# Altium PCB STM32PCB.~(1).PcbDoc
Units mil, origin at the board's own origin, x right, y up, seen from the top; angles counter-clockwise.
Board outline 2110.03 x 910.03 mil, 2 copper layers (Top Layer, Bottom Layer), stack 65.792 mil thick; 30 components, 49 nets, 163 pads, 181 vias.
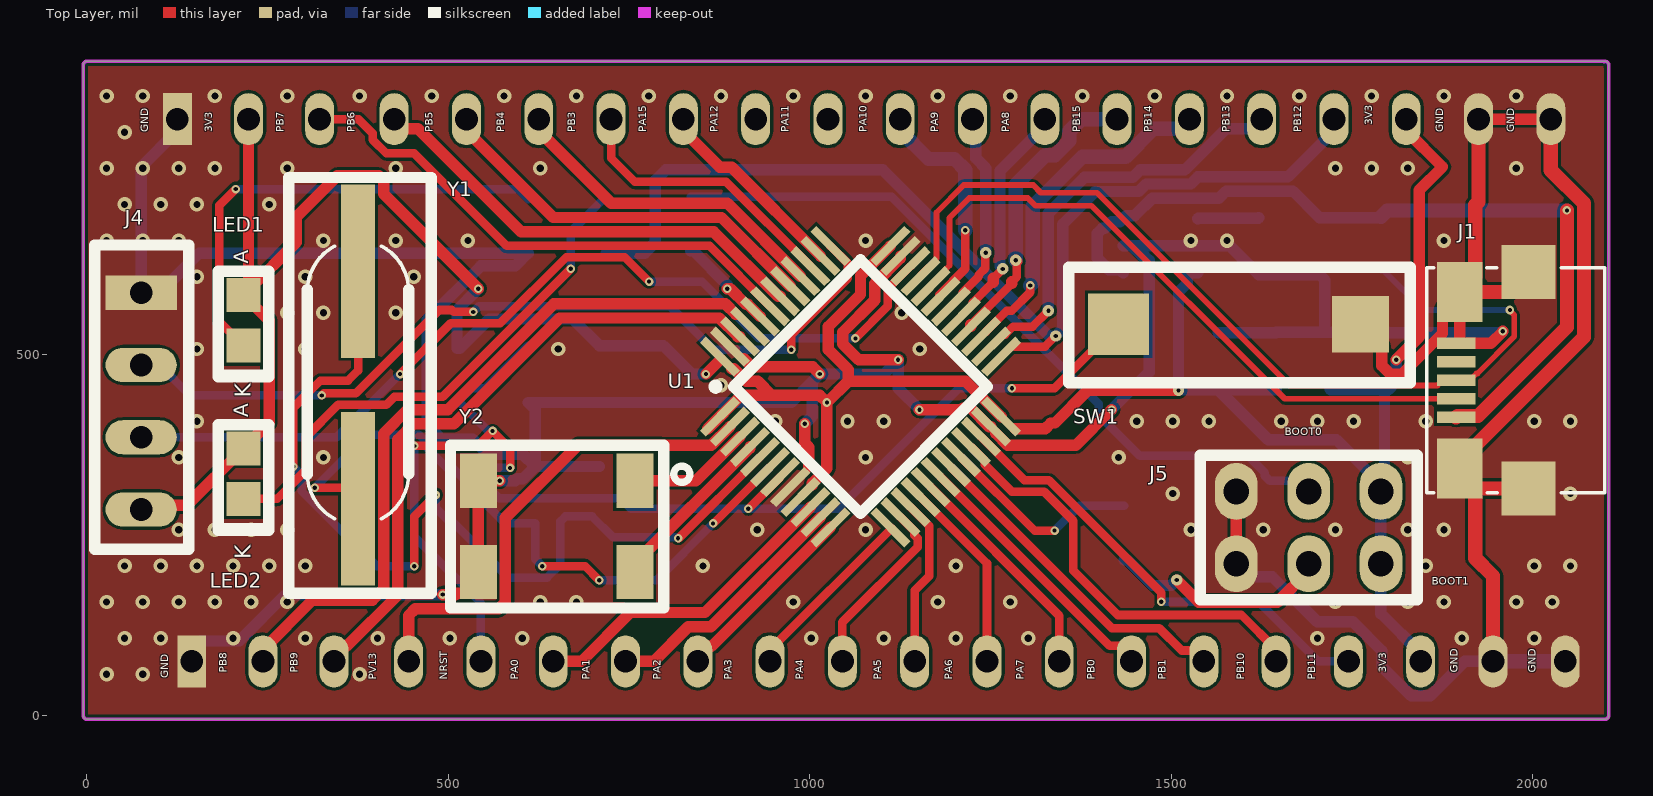
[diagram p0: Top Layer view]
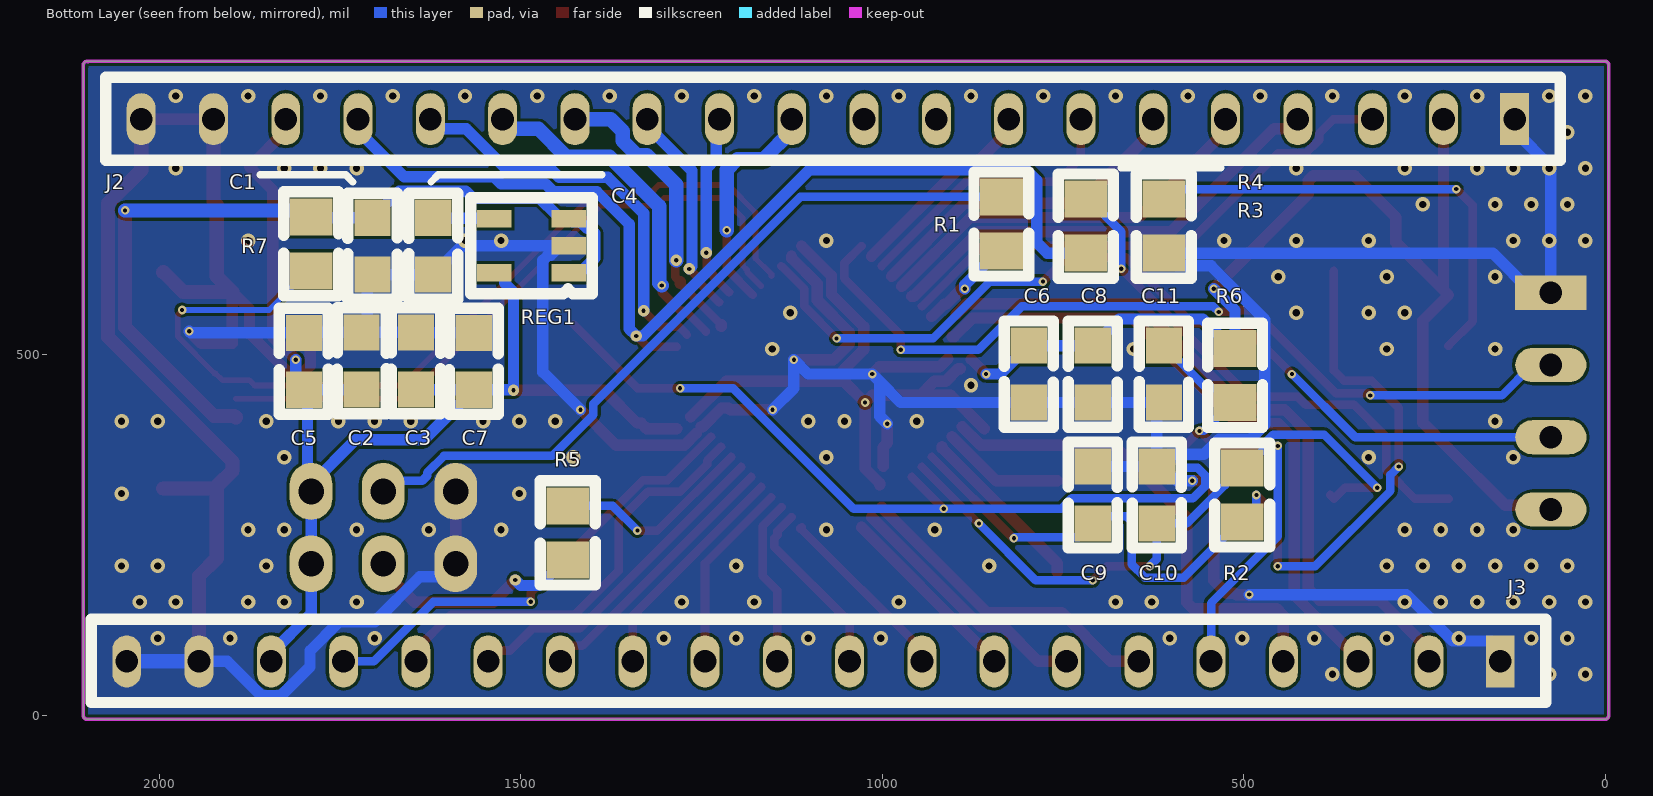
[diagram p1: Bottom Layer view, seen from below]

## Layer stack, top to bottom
Top Solder: solder mask 0.4, Solder Resist, Dk 3.5
Top Layer: signal copper 1.4
Dielectric 1: dielectric 62.9921, FR-4, Dk 4.8
Bottom Layer: signal copper 1.4
Bottom Solder: solder mask 0.4, Solder Resist, Dk 3.5

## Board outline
-5.02,0 -5.02,900 cw(c0,900) 0,905.01 2097.07,905.01 2098.54,904.8 cw(c2100,900) 2105.01,900 2105.01,0 cw(c2100,0) 2100,-5.02 2.14,-5.02 1.07,-4.9 cw(c0,0)

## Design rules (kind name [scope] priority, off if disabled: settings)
Clearance [All] p1: gap=3.94 ignorepadtopadclearanceinfootprint=TRUE
DiffPairsRouting DiffPair_90DiffPairsRouting [InDifferentialPairClass('diff_90')] p1: maxlimit=10 minlimit=10 mostfreqgap=10 toplayer_minwidth=8 toplayer_maxwidth=8 toplayer_prefwidth=8 bottomlayer_minwidth=8 bottomlayer_maxwidth=8 bottomlayer_prefwidth=8 maxuncoupledlength=500
DiffPairsRouting [All] p2: maxlimit=10 minlimit=10 mostfreqgap=10 toplayer_minwidth=15 toplayer_maxwidth=15 toplayer_prefwidth=15 bottomlayer_minwidth=15 bottomlayer_maxwidth=15 bottomlayer_prefwidth=15 maxuncoupledlength=500
MatchedLengths DiffPair_90MatchedLengths [InDifferentialPairClass('diff_90')] p1: tolerance=1000 checknetsindiffpair=FALSE checkdiffpairvsdiffpair=TRUE checkxsignals=TRUE checkothers=TRUE
PolygonConnect [All] p1: connectstyle=Direct reliefconductorwidth=10 reliefentries=4 polygonreliefangle="90 Angle" airgapwidth=10
RoutingVias [All] p1: holewidth=8 width=15 viastyle="Through Hole" minholewidth=5 minwidth=10 maxholewidth=10 maxwidth=20
SolderMaskExpansion [All] p1: expansion=4 istentingtop=FALSE
Width [All] p1: maxlimit=39.37 minlimit=11.81 preferedwidth=19.68
29 further rules are at their usual default settings.

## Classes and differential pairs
differential pair class diff_90: D
component class Controller_Page: C5 C6 C7 C8 C9 C10 C11 J5 LED1 LED2 R1 R2 R3 R4 R5 R6 SW1 U1 Y1 Y2
component class Connector_Page: C1 C2 C3 C4 J1 J2 J3 R7 REG1
differential pair D: +D_P -D_N

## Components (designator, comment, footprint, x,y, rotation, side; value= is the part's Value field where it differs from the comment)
C1 "0.1uF" CAP_0805 1705,649.37 r90 bottom
C2 "0.1uF" CAP_0805 1720,490.63 r270 bottom
C3 "1uF" CAP_0805 1645,490.63 r270 bottom
C4 "22pF" CAP_0805 1620.87,649.37 r90 bottom
C5 "0.1uF" CAP_0805 1800,490 r270 bottom
C6 "0.1uF" CAP_0805 797.24,472.44 r90 bottom
C7 "0.1uF" CAP_0805 1565,490 r270 bottom
C8 "0.1uF" CAP_0805 708.66,472.44 r90 bottom
C9 "22pF" CAP_0805 708.66,305.12 r270 bottom
C10 "22pF" CAP_0805 620.08,305.12 r270 bottom
C11 "0.1uF" CAP_0805 610.23,472.44 r90 bottom
J1 "MICRO USB2.0" CON_10118192-0001LF_SMD 1944.12,463.8 r90 top
J2 "20X1 Bergstrip" CON20_100_40D72_TH_ST 125,825 r270 bottom locked
J3 "20X1 Bergstrip" CON20_100_40D72_TH_ST 145,75 r270 bottom locked
J4 "4X1 Bergstrip" CON4_100_40D72_TH_ST_MALE 75,585 r0 top
J5 "2X3 Berg Strip" CON6_100_59D78_TH_ST_Duplicate 1790,310 r180 top
LED1 "RED LED" LED_0805 216.53,546.81 r90 top
LED2 "RED LED" LED_0805 216.54,334.65 r90 top
R1 "10K" RES_0805 835,680 r270 bottom
R2 "10Mohm" RES_0805 501.97,305.12 r270 bottom
R3 "1K" RES_0805 610.24,677.17 r270 bottom
R4 "1K" RES_0805 718.51,677.17 r270 bottom
R5 "10K" RES_0805 1435,252.6 r90 bottom
R6 "10K" RES_0805 511.81,470.48 r270 bottom
R7 "10K" RES_0805 1790,652.6 r270 bottom
REG1 "RT9193-33GB" SOT23-5 1485,650 r90 bottom
SW1 "TACT SWITCH" SW_342_SMD 1761.81,541.34 r0 top
U1 "STM32F103C8T6" LQFP-48_19.6_393_58X11_SMD 1070,455 r45 top locked
Y1 "8MHz" XTAL_314_240X47_SMD 375,614.96 r270 top locked
Y2 "32.768KHz" "XTAL_MC-405 32.7680K-G3" 757.87,198.82 r180 top

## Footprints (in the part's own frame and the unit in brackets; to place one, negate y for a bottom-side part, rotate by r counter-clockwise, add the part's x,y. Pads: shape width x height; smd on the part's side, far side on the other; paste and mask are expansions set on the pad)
CAP_0805 [mil] "Ceramic Capacitor"
  rect 50x50 smd mask+3: 1(-39.37,0) 2(39.37,0)
  silkscreen extent -73,-34 73,34, body extent -39,-25 39,25, height 31
CON4_100_40D72_TH_ST_MALE [mm] "Berg Strip"
  rect 2.5x1.2 hole 0.8: 1(0,0)
  oval 2.5x1.2 hole 0.8: 2(0,-2.54) 3(0,-5.08) 4(0,-7.62)
  round 1.016 on Top Overlay: ""(2.311,0.178)
  silkscreen extent -1.63,-9.02 1.68,1.68, body extent -1.14,-8.76 1.4,1.4, height 8.55
CON6_100_59D78_TH_ST_Duplicate [mm] "Berg strip"
  oval 1.5x2 hole 0.9: 1(0,0) 2(0,2.54) 3(2.54,0) 4(2.54,2.54) 5(5.08,0) 6(5.08,2.54)
  silkscreen extent -1.27,-1.27 6.35,3.81, body extent -1.07,-1.27 6.15,3.56, height 8.18
CON20_100_40D72_TH_ST [mil] "Berg strip"
  rect 72x40 hole 31.5: 1(0,0)
  oval 72x40 hole 31.5: 2(0,-98.43) 3(0,-196.85) 4(0,-300) 5(0,-400) 6(0,-500) 7(0,-600) 8(0,-700) 9(0,-800) 10(0,-900) 11(0,-1000) 12(0,-1100) 13(0,-1200) 14(0,-1300) 15(0,-1400) 16(0,-1500) 17(0,-1600) 18(0,-1700) 19(0,-1800) 20(0,-1900)
  round 40 on Bottom Overlay: ""(83,2.57)
  silkscreen extent -58,-1949 57,63, body extent -51,-1949 47,51, height 323
CON_10118192-0001LF_SMD [mm] "USB2.0 MICRO"
  rect 0.4x1.35 smd: 1(-1.3,1.275) 2(-0.65,1.275) 3(0,1.275) 4(0.65,1.275) 5(1.3,1.275)
  rect 2.1x1.6 smd: 6(-3.1,1.15) 7(3.1,1.15)
  rect 1.9x1.9 smd: 8(-3.8,-1.275) 9(3.8,-1.275)
  silkscreen extent -3.95,-3.94 3.95,2.3, body extent -4.04,-3.94 4.04,1.66, height 2.81
LED_0805 [mm] "LED"
  rect 1.2x1.2 smd mask+0.076: A(0.889,0) K(-0.889,0)
  silkscreen extent -1.99,-0.89 1.73,0.89, body extent -1.01,-0.62 1.01,0.63, height 1.1
LQFP-48_19.6_393_58X11_SMD [mm] "48LQFP"
  rect 1.7x0.3 smd mask+0.076: 1(-4.238,2.75) 2(-4.238,2.25) 3(-4.238,1.75) 4(-4.238,1.25) 5(-4.238,0.75) 6(-4.238,0.25) 7(-4.238,-0.25) 8(-4.238,-0.75) 9(-4.238,-1.25) 10(-4.238,-1.75) 11(-4.238,-2.25) 12(-4.238,-2.75) 25(4.238,-2.75) 26(4.238,-2.25) 27(4.238,-1.75) 28(4.238,-1.25) 29(4.238,-0.75) 30(4.238,-0.25) 31(4.238,0.25) 32(4.238,0.75) 33(4.238,1.25) 34(4.238,1.75) 35(4.238,2.25) 36(4.238,2.75)
  rect 0.3x1.7 smd mask+0.076: 13(-2.75,-4.238) 14(-2.25,-4.238) 15(-1.75,-4.238) 16(-1.25,-4.238) 17(-0.75,-4.238) 18(-0.25,-4.238) 19(0.25,-4.238) 20(0.75,-4.238) 21(1.25,-4.238) 22(1.75,-4.238) 23(2.25,-4.238) 24(2.75,-4.238) 37(2.75,4.238) 38(2.25,4.238) 39(1.75,4.238) 40(1.25,4.238) 41(0.75,4.238) 42(0.25,4.238) 43(-0.25,4.238) 44(-0.75,4.238) 45(-1.25,4.238) 46(-1.75,4.238) 47(-2.25,4.238) 48(-2.75,4.238)
  silkscreen extent -3.72,-3.15 3.15,3.72, body extent -4.5,-4.5 4.5,4.5, height 1.7
RES_0805 [mm] "Resister"
  rect 1.3x1.5 smd mask+0.076: 1(0.95,0) 2(-0.95,0)
  silkscreen extent -1.83,-0.97 1.83,0.97, body extent -1,-0.63 1,0.62, height 0.5
SOT23-5 [mm] "CASE: SOT"
  rect 0.62x1.22 smd mask+0.076: 1(-0.953,-1.31) 2(-0.003,-1.31) 3(0.947,-1.31) 4(0.952,1.31) 5(-0.953,1.31)
  silkscreen extent -1.69,-2.14 1.69,2.14, body extent -1.5,-1.5 1.5,1.5, height 1.41
SW_342_SMD [mm] "CASE: SMD"
  rect 2x2 smd: 1(0,0)
  rect 2.15x2.15 smd: 2(-8.5,0)
  silkscreen extent -10.25,-2.06 1.75,2, body extent -7.17,-1.79 -1.17,1.71, height 2.4
XTAL_314_240X47_SMD [mm] "CASE: TH"
  rect 6.096x1.2 smd: 1(0,0) 2(8,0)
  silkscreen extent -3.29,-2.44 11.32,2.57, body extent -2.99,-2.27 10.9,2.41, height 3.05
"XTAL_MC-405 32.7680K-G3" [mm] "Crystal"
  rect 1.3x1.9 smd: 1(0,-3.2) 2(5.5,-3.2) 3(5.5,0) 4(0,0)
  silkscreen extent -1.93,-4.44 6.48,1.27, body extent -1.02,-4.44 6.48,1.27, height 3.6

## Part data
C1 C2 C5 C6 C7 C8 C11: library part CAP_0.1uF-50V-5%-0805, "0.1µF ±5% 50V Ceramic Capacitor X7R 0805 (2012 Metric)", Case/Package="0805 (2012 Metric)", Manufacturer=KEMET, Manufacturing Part Number=C0805C104J5RACTU, Supplier Part Number-1=399-1171-1-ND
C3: library part CAP_1uF-50V-5%-0805, "1µF ±5% 50V Ceramic Capacitor X7R 0805 (2012 Metric)", Case/Package="0805 (2012 Metric)", Manufacturer=Yageo, Manufacturing Part Number=CC0805JKX7R9BB105, Supplier Part Number-1=311-3498-1-ND
C4 C9 C10: library part CAP_22pF-50V-5%-0805, "22pF ±5% 50V Ceramic Capacitor C0G, NP0 0805 (2012 Metric)", Case/Package=0805, Manufacturer=KEMET, Manufacturer Part Number=C0805C220J5GACTU, Supplier Part Number-1=399-1113-1-ND
J1: library part CON-USB_10118192-0002LF-SMD, "USB - micro B USB 2.0 Receptacle Connector 5 Position Surface Mount, Right Angle", Case/Package=SMD, Manufacturer="Amphenol ICC (FCI)", Manufacturing Part Number=10118192-0002LF, Supplier Part Number-1=609-5379-1-ND
J2 J3: library part CON-BS-PLG_20X1-100-TH-ST, "20 pin, 1 row, 2.54mm pitch bergstrip", Case/Package=TH, Manufacturer=NA
J4: library part CON-BS-PLG_4X1-100-TH-ST, "4 pin, 1 row, 2.54mm pitch bergstrip", Case/Package=TH, Manufacturer=NA
J5: library part CON-BS-PLG_2X3-100-TH-ST, "6 pin, 2 row, 2.54mm pitch bergstrip", Case/Package=TH, Manufacturer=NA
LED1 LED2: library part LED-RED_10mA-0805, "Red 621nm LED Indication - Discrete 2V 0805 (2012 Metric)", Case/ Package=0805, Manufacturer="Lite-On Inc.", Manufacturer Part Number=LTST-C170EKT, Supplier Part Number-1=160-1178-1-ND
R1 R5 R6 R7: library part RES_10K-0.125W-1%-0805, "10 kOhms ±1% 0.125W, 1/8W Chip Resistor 0805 (2012 Metric) Moisture Resistant Thick Film", Case/Package=0805, Manufacturer=Yageo, Manufacturing Part Number=RC0805FR-0710KL, Supplier Part Number-1=311-10.0KCRCT-ND
R2: library part RES_10MOHM-0.125W-1%-0805, "10 MOhms ±1% 0.125W, 1/8W Chip Resistor 0805 (2012 Metric) Automotive AEC-Q200, High Voltage Thick Film", Case/Package="0805 (2012 Metric)", Manufacturer="Rohm Semiconductor", Manufacturing Part Number=KTR10EZPF1005, Supplier Part Number-1=RHM10.0MAHCT-ND
R3 R4: library part RES_1K-0.125W-1%-0805, "1 kOhms ±1% 0.125W, 1/8W Chip Resistor 0805 (2012 Metric) Moisture Resistant Thick Film", Case/Package=0805, Manufacturer=垈㎵á, Manufacturer Part Number=RC0805FR-071KL, Supplier Part Number-1=311-1.00KCRCT-ND
REG1: library part REG_3.3V-5.5V-0.3A-SOT-23-5, "Linear Voltage Regulator IC 1 Output 300mA SOT-23-5", Case/ Package=SOT-23-5, Manufacturer="Richtek USA Inc.", Supplier Part Number-1=1028-1014-1-ND
SW1: library part SW_KSR223GLFG-SMD, "Tactile Switch SPST-NO Top Actuated Surface Mount", Case/Package=SMD, Manufacturer=C&K, Manufacturing Part Number=KSR223GLFG, Supplier Part Number-1=401-1704-1-ND
U1: library part "IC-STM32F103C8T6 _1", "ARM® Cortex®-M3 STM32F1 Microcontroller IC 32-Bit 72MHz 64KB (64K x 8) FLASH", Case/Package=48-LQFP, Manufacturer=STMicroelectronics, Supplier Part Number-1=497-6063-ND
Y1: library part XTAL_8MHZ-LFXTAL030234, "Crystals 8MHz 22pF -20C 70C", Case/Package=SMD, Manufacturer="IQD Frequency Products", Manufacturing Part Number=LFXTAL030234Reel, Supplier Part Number-1=449-LFXTAL030234REEL
Y2: library part "XTAL_32.768KHz-MC-405 32.7680K-G3", "Crystals SMD AT XTL MHZ +/-50PPM 12.5 PF 250 T/R", Case/Package=SMD, Manufacturer=Epson, Manufacturing Part Number="MC-405 32.7680K-G3: ROHS", Supplier Part Number-1=732-MC405327680KG3RS

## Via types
v1: diameter 20, hole 10, Top Layer to Bottom Layer, tented both sides, 134 vias
v2: diameter 11.81, hole 5.91, Top Layer to Bottom Layer, 40 vias
v3: diameter 15.75, hole 5.91, Top Layer to Bottom Layer, 7 vias

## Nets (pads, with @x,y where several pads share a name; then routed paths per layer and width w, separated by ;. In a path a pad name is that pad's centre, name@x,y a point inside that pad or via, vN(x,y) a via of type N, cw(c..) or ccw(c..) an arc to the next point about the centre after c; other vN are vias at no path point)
+3V3: C2.2 C3.2 C5.2 C6.2 C7.2 C8.2 J2.2 J2.18 J3.18 J4.4 J5.1 J5.2 LED1.A LED2.A R6.2 REG1.5 U1.1 U1.9 U1.24 U1.36 U1.48 | length 4317
  Top Layer w15.75: J4.4 81.03,291.03 137.92,291.03 LED2.A 251.97,405.08 251.97,546.38 LED1.A LED1.A@223.43,588.7 ; J2.2 LED1.A@223.43,588.7 ; v2(541.34,590.55) 410.43,721.46 410.43,739.85 403.51,746.77 346.49,746.77 289.38,689.67 289.38,654.66 LED1.A@223.43,588.7 ; v2(856.3,472.44) U1.48@876.48,492.62 ; U1.1@858.76,396.87 904.8,442.91 947.5,442.91 ; U1.48@892.17,479.72 894.95,479.72 912.07,462.6 927.82,462.6 947.5,442.91 ; U1.9@1003.52,318.92 1003.52,321.71 1023.62,341.81 v2(1023.62,433.07) ; U1.36 1070.05,608.17 1070.05,582.68 1025.59,538.22 1025.59,506.16 1053.15,478.6 1053.15,462.6 ; U1.24 1215.52,462.6 1053.15,462.6 ; U1.24@1284.03,396.87 1325.67,396.87 1333.46,404.66 1339.03,404.66 1384.37,450 v3(1510,450) ; v2(1811.02,492.13) 1843.01,524.11 1843.01,727.01 1875,759 1825,809 J2.18 ; 947.5,442.91 1013.78,442.91 v2(1023.62,433.07) ; v2(1023.62,433.07) 1053.15,462.6
  Bottom Layer w15.75: J4.4 J4.4@100.59,285 ; v2(541.34,590.55) 511.81,561.02 R6.2 515.75,507.87 556.5,548.62 671.86,548.62 C8.2 C6.2 836.62,472.44 v2(856.3,472.44) ; REG1.5 1524.76,612.5 1522.4,610.13 1522.4,598.32 1510,585.93 v3(1510,450) 1510.63,450.63 C7.2 ; C3.2 1644.68,450.94 1565.31,450.94 C7.2 ; C2.2 1720.32,450.94 C5.2@1799.68,450.94 ; J5.1@1795,319.84 C5.2@1795,446.26 ; C5.2 1811.02,461.65 v2(1811.02,492.13) ; J3.18 1845,86.1 1790,141.1 J5.2 J5.1 1790,319.84 1728.42,381.42 1634.2,381.42 C7.2
+5V: C1.2 J1.1 R7.2 REG1.1 REG1.3 | length 1137.2
  Top Layer w19.68: J1.1 1895.89,414.58 1924.23,414.58 2047.24,537.59 v2(2047.24,698.82)
  Bottom Layer w15.75: REG1.1 1429.09,616.83 1413.57,616.83 1397.6,632.8 1397.6,667 1404.51,673.91 1408.22,673.91 1417.28,682.97 1429.09,682.97 1437.75,691.63 1449.56,691.63 1473.56,715.63 1565.92,715.63 1575.84,725.55 1668.19,725.55 C1.2@1704.37,689.37 ; C1.2 1788.74,688.74 R7.2
  Bottom Layer w19.68: R7.2 1798.82,698.82 v2(2047.24,698.82)
BOOT0: J5.3 R1.2 | length 1035.3
  Bottom Layer w11.81: R1.2 1113.31,717.4 1399.61,431.1 1399.61,415.89 1456.28,359.21 1606.31,359.21 1629.37,336.15 1629.37,331.72 1636.29,324.8 1675.2,324.8 J5.3
BOOT1: J5.4 R5.2 | length 313.2
  Top Layer w15.75: v3(1507.5,187.5) 1538.15,156.85 1646.69,156.85 1690,200.16 J5.4
  Bottom Layer w15.75: R5.2 1438.94,215.2 1474.13,180 1500,180 v3(1507.5,187.5)
D_N: J1.2 U1.32 | length 932.6
  Top Layer w8: U1.32 1186.59,613.35 1186.59,616.04 1193.04,622.49 1193.04,688.49 1220.36,715.81 1301.55,715.81 1312.09,705.27 1389.73,705.27 1656.79,438.21 J1.2
D_P: J1.3 R7.1 U1.33 | length 1295.3
  Top Layer w8: U1.33 1153.18,610.47 1175.04,632.33 1175.04,695.95 1212.9,733.81 1309,733.81 1319.54,723.27 1397.18,723.27 1663.83,456.63 1868.05,456.63 1875.22,463.8 1912.62,463.8 1922.15,473.33 1923.53,473.33 1974.47,524.27 1974.47,554.02 1968.5,559.99 v2(1968.5,561.02)
  Bottom Layer w8: R7.1 1793.94,615.2 1848.11,561.02 v2(1968.5,561.02)
GND: C1.1 C2.1 C3.1 C4.1 C5.1 C6.1 C7.1 C8.1 C9.1 C10.1 C11.1 J1.5 J1.6 J1.7 J1.8 J1.9 J2.1 J2.19 J2.20 J3.1 J3.19 J3.20 J4.1 J5.5 J5.6 R3.1 REG1.2 SW1.1 U1.8 U1.23 U1.35 U1.47 Y2.2 Y2.3 | length 7026
  Top Layer w15.75: v2(492.13,167.32) 509.84,167.32 511.81,169.29 523.62,169.29 541.34,187.01 Y2.2 v2(570.87,324.8) ; U1.47@908.87,493.64 920.23,482.28 1003.94,482.28 v2(1013.78,472.44) ; v2(992.86,403.54) 992.86,376.98 998.63,371.22 998.63,344.65 ; v2(1122.05,492.13) 1067.46,492.13 1045.28,514.32 1045.28,530.06 1089.74,574.53 1089.74,597.23 1125.34,632.83 U1.35 ; v2(1151.57,423.23) 1210.16,423.23 1212.32,425.39 1222.1,425.39 1247.83,399.66 U1.23 ; U1.23@1256.82,390.67 1273.56,373.93 1368.02,373.93 v2(1417.32,423.23) ; J5.6 J5.5 ; SW1.1 1791.34,511.81 1791.34,483.97 1802.87,472.44 1819.18,472.44 1875.22,528.48 1875.22,562.22 J1.7 1898.84,514.98 1942.14,514.98 v2(1958.66,531.5) ; J2.19 J2.20
  Top Layer w19.68: J2.19 1925,710.73 1920.5,706.23 1920.5,607.5 J1.7 1966.76,585.84 J1.9 ; J3.19 1945,193.07 1920.5,217.57 J1.6@1920.5,314.19 ; J1.8 J1.6@1920.5,314.19 ; J2.20 2025,754.47 2070.87,708.6 2070.87,523.62 1898.84,351.59 J1.6 1898.84,338.8 1920.5,317.14 J1.6@1920.5,314.19
  Bottom Layer w15.75: J2.1 125,809 75,759 J4.1 100.59,585 155.35,639.76 R3.1 592.52,622.05 545,622.05 470.47,547.52 470.47,402.59 490.58,382.49 533.82,382.49 554.69,361.61 602.95,361.61 C10.1 ; J3.1 145,91 157.13,103.13 210.56,103.13 274.76,167.32 v2(492.13,167.32) ; v2(570.87,324.8) 592.57,324.8 595.13,327.36 602.95,327.36 C10.1 ; C9.1 C10.1 ; v2(992.86,403.54) 1003.32,414 1003.32,461.98 ; v2(1151.57,423.23) 1122.05,452.76 v2(1122.05,492.13) 1102.36,472.44 v2(1013.78,472.44) 1003.32,461.98 ; v2(1417.32,423.23) 1469.25,475.15 1469.25,629.59 1462.33,636.51 1458.62,636.51 REG1.2@1445.23,649.9 ; REG1.2 REG1.2@1445.23,649.9 ; C7.1 1565.31,529.68 1644.68,529.68 C3.1 C2.1 1799.36,530 C5.1 1956.53,529.37 v2(1958.66,531.5) ; J5.6 1608.13,191.87 1639.82,191.87 1701.86,129.83 1751.15,129.83 1791.49,89.5 1791.49,67.52 1831.82,27.19 1858.18,27.19 1905.99,75 J3.19 ; C2.1@1712.5,537.5 1712.5,602.5 C1.1 C4.1 1580.97,649.9 REG1.2@1445.23,649.9 ; C10.1 620.08,423.23 C11.1 C8.1 C6.1 974.41,433.07 1003.32,461.98
  Bottom Layer w19.68: J3.19 J3.20
  other v1: 27.07,57.07 77.07,57.07 377.07,57.07 52.07,107.07 102.07,107.07 202.07,107.07 302.07,107.07 402.07,107.07 502.07,107.07 602.07,107.07 1002.07,107.07 1102.07,107.07 1202.07,107.07 1302.07,107.07 1702.07,107.07 1902.07,107.07 2002.07,107.07 27.07,157.07 77.07,157.07 127.07,157.07 177.07,157.07 227.07,157.07 277.07,157.07 627.07,157.07 677.07,157.07 977.07,157.07 1177.07,157.07 1277.07,157.07 1727.07,157.07 1827.07,157.07 1877.07,157.07 1977.07,157.07 2027.07,157.07 52.07,207.07 102.07,207.07 152.07,207.07 202.07,207.07 252.07,207.07 302.07,207.07 852.07,207.07 1202.07,207.07 1852.07,207.07 2002.07,207.07 2052.07,207.07 127.07,257.07 177.07,257.07 227.07,257.07 277.07,257.07 927.07,257.07 1077.07,257.07 1527.07,257.07 1627.07,257.07 1727.07,257.07 1827.07,257.07 1877.07,257.07 1502.07,307.07 2052.07,307.07 127.07,357.07 327.07,357.07 1077.07,357.07 1427.07,357.07 1827.07,357.07 152.07,407.07 952.07,407.07 1052.07,407.07 1102.07,407.07 1452.07,407.07 1502.07,407.07 1552.07,407.07 1652.07,407.07 1702.07,407.07 1752.07,407.07 1852.07,407.07 2002.07,407.07 2052.07,407.07 877.07,457.07 152.07,507.07 302.07,507.07 652.07,507.07 1152.07,507.07 277.07,557.07 327.07,557.07 427.07,557.07 1127.07,557.07 152.07,607.07 302.07,607.07 452.07,607.07 27.07,657.07 77.07,657.07 127.07,657.07 327.07,657.07 427.07,657.07 527.07,657.07 1077.07,657.07 1527.07,657.07 1577.07,657.07 1877.07,657.07 52.07,707.07 102.07,707.07 152.07,707.07 252.07,707.07 27.07,757.07 77.07,757.07 127.07,757.07 177.07,757.07 277.07,757.07 427.07,757.07 627.07,757.07 1727.07,757.07 1777.07,757.07 1827.07,757.07 1977.07,757.07 52.07,807.07 27.07,857.07 77.07,857.07 177.07,857.07 277.07,857.07 377.07,857.07 477.07,857.07 577.07,857.07 677.07,857.07 777.07,857.07 877.07,857.07 977.07,857.07 1077.07,857.07 1177.07,857.07 1277.07,857.07 1377.07,857.07 1477.07,857.07 1577.07,857.07 1677.07,857.07 1777.07,857.07 1877.07,857.07 1977.07,857.07
NetC4_2: C4.2 REG1.4 | length 84.8
  Bottom Layer w15.75: REG1.4 1537.19,688.12 1620.25,688.12 C4.2
NetLED1_K: LED1.K R3.2 | length 650
  Top Layer w11.81: v2(205.71,728.35) 183.07,705.71 183.07,545.28 LED1.K
  Bottom Layer w11.81: v2(205.71,728.35) 596.46,728.35 R3.2
NetLED2_K: LED2.K R4.2 | length 730.6
  Top Layer w11.81: LED2.K 262.86,299.65 302.59,339.37 302.59,385.13 347.3,429.84 414.16,429.84 425.26,440.94 492.13,440.94 v2(669.29,618.11)
  Bottom Layer w11.81: v2(669.29,618.11) 669.29,669.29 714.57,714.57 R4.2
NetR1_1: R1.1 U1.44 | length 136.6
  Top Layer w15.75: v2(885.83,590.55) 889.91,590.55 911.65,568.81 914.44,568.81 U1.44
  Bottom Layer w15.75: R1.1 838.93,642.6 885.83,595.7 v2(885.83,590.55)
NetR5_1: R5.1 U1.20 | length 282.5
  Top Layer w11.81: U1.20 1310.85,255.91 v2(1338.58,255.91)
  Bottom Layer w11.81: v2(1338.58,255.91) 1372.68,290 R5.1
NRST: C11.2 J3.5 R6.1 SW1.2 U1.7 | length 1838.1
  Top Layer w11.81: v2(452.76,372.98) 540.3,372.98 v2(561.02,393.7) 585.24,369.49 v2(585.24,342.52) ; J3.5 545,77.57 J3.5@558.02,90.59 ; v2(914.85,285.93) U1.7 ; v2(1279.53,452.76) 1338.58,452.76 SW1.2
  Bottom Layer w11.81: v2(452.76,372.98) 452.76,247.89 545,155.64 J3.5 ; v2(561.02,393.7) 555.12,393.7 515.75,433.07 R6.1 531.5,452.76 551.18,452.76 C11.2 ; v2(585.24,342.52) 563.53,342.52 553.15,332.14 553.15,317.46 570.02,300.59 737.74,300.59 752.39,285.93 v2(914.85,285.93) 1039.34,285.93 1206.16,452.76 v2(1279.53,452.76)
PA0: J3.6 U1.10 | length 444.1
  Top Layer w15.75: J3.6 684.01,75 751.51,142.5 854.93,142.5 U1.10
PA1: J3.7 U1.11 | length 352.2
  Top Layer w15.75: J3.7 784.01,75 831.82,122.81 863.09,122.81 U1.11
PA2: J3.8 U1.12 | length 265.9
  Top Layer w15.75: J3.8 845,84.44 856.2,95.64 863.75,95.64 U1.12
PA3: J3.9 U1.13 | length 255.6
  Top Layer w12: J3.9 945,91 1112.88,258.88 1112.88,259.01 U1.13
PA4: J3.10 U1.14 | length 252.4
  Top Layer w12: J3.10 1045,129 1149.2,233.2 1149.2,245.09 1144.7,249.59 1144.7,255.03 U1.14
PA5: J3.11 U1.15 | length 232.4
  Top Layer w12: U1.15 1139.26,288.17 1165.14,262.29 1165.14,193.18 1145,173.05 J3.11
PA6: J3.12 U1.16 | length 265.3
  Top Layer w12: U1.16 1245,210.4 J3.12
PA7: J3.13 U1.17 | length 314.8
  Top Layer w12: U1.17 1345,138.24 J3.13
PA8: J2.13 U1.29 | length 297.7
  Top Layer w11.81: U1.29@1225.56,571.59 1253.6,599.63 ; 1253.6,604.72 v3(1266.77,617.89)
  Top Layer w15.75: 1253.6,599.63 1253.6,604.72
  Bottom Layer w15.75: v3(1266.77,617.89) 1263.07,621.59 1263.07,753.63 1325,815.56 J2.13
PA9: J2.12 U1.30 | length 260.3
  Top Layer w11.81: U1.30@1211.64,585.51 1233.92,607.78 1233.92,610.09 1242.63,618.8 1242.63,639.46 v3(1243.39,640.22)
  Bottom Layer w15.75: J2.12 1229.64,820.36 1229.64,770.98 1243.39,757.24 v3(1243.39,640.22)
PA10: J2.11 U1.31 | length 316.3
  Top Layer w11.81: U1.31@1178.98,581.98 1215,617.99 v2(1215,671.39)
  Bottom Layer w19.68: J2.11 1125,809 1164,770 1200,770 1215,755 v2(1215,671.39)
PA11: J2.10
PA12: J2.9
PA15: J2.8 U1.38 | length 277.5
  Top Layer w15.75: J2.8 825,809 875.59,758.41 891.86,758.41 U1.38
PB0: J3.14 U1.18 | length 374.6
  Top Layer w12: U1.18 1414.72,96.36 1432.07,96.36 1445,83.42 J3.14
PB1: J3.15 U1.19 | length 462.7
  Top Layer w12: U1.19 1417.98,120.94 1483.39,120.94 1514.3,90.04 1532.07,90.04 1545,77.1 J3.15
PB3: J2.7 U1.39 | length 391.4
  Top Layer w11.81: J2.7 725,771.28 758.09,738.19 884.25,738.19 U1.39
PB4: J2.6 U1.40 | length 461.2
  Top Layer w15.75: J2.6 625,809 725.34,708.66 875.98,708.66 885.94,708.66 U1.40
PB5: J2.5 U1.41 | length 553
  Top Layer w15.75: J2.5 525,809 645.02,688.98 877.78,688.98 U1.41
PB6: J2.4 U1.42 | length 636.7
  Top Layer w15.75: J2.4 425,822.95 436.2,811.75 457.94,811.75 600.39,669.29 866.84,669.29 956.19,579.94 U1.42
PB7: J2.3 U1.43 | length 735.7
  Top Layer w11.81: J2.3 375.79,825 395.16,805.63 395.16,796.64 414.24,777.56 452.76,777.56 580.71,649.61 861.47,649.61 U1.43
PB8: J3.2 U1.45 | length 1000.6
  Top Layer w15.75: J3.2 243.43,91 312.14,159.71 395.04,159.71 410.43,175.11 410.43,390.08 443.58,423.23 499.46,423.23 645.91,569.68 882.94,569.68 U1.45@897.73,554.89
PB9: J3.3 U1.46 | length 900.3
  Top Layer w15.75: J3.3 341.85,84.44 353.05,95.64 358.8,95.64 430.12,166.95 430.12,381.93 451.73,403.54 507.62,403.54 654.07,549.99 874.79,549.99 900.52,524.26 U1.46
PB10: J3.16 U1.21 | length 598.1
  Top Layer w12: U1.21 1242.13,352.46 1242.13,347.03 1279.49,309.67 1324.19,309.67 1364.27,269.59 1364.27,200.69 1425.92,139.04 1596.96,139.04 1645,91 J3.16
PB11: J3.17 U1.22 | length 644.4
  Top Layer w11.81: U1.22 1296.92,325.51 1330.75,325.51 1486.22,170.04 v2(1486.22,157.48)
  Bottom Layer w11.81: v2(1486.22,157.48) 1620.72,157.48 1703.2,75 J3.17
PB12: J2.17 R4.1 U1.25 | length 1480.4
  Top Layer w11.81: U1.25@1284.03,510.34 1325.34,510.34 v3(1340,525)
  Bottom Layer w15.75: R4.1 771.65,639.76 786.12,654.23 786.12,740.34 800.58,754.8 1100.96,754.8 1330.76,525 v3(1340,525) 1350,535 1350,680 1395,725 1455.09,725 1465.41,735.32 1526.93,735.32 1536.85,745.24 1661.24,745.24 1725,809 J2.17
PB13: J2.16 U1.26 | length 559.6
  Top Layer w11.81: U1.26@1270.11,527.05 1281.1,538.04 1308.04,538.04 v3(1330,560)
  Bottom Layer w15.75: v3(1330,560) 1330,694.91 1379.78,744.68 1446.94,744.68 1457.26,755 1518.77,755 1575.47,811.7 1615.62,811.7 1625,821.09 J2.16
PB14: J2.15 U1.27 | length 496.6
  Top Layer w11.81: U1.27@1243.72,531.28 1272.13,559.7 1279.07,559.7 1305,585.62 v2(1305,595)
  Top Layer w19.68: J2.15@1515.62,805.11 1525,814.5 J2.15
  Bottom Layer w19.68: v2(1305,595) 1308.35,598.35 1308.35,704.4 1345,741.05 1377.03,773.08 1436.85,773.08 1475.47,811.7 1515.62,811.7 1525,821.09 J2.15
PB15: J2.14 U1.28 | length 408.8
  Top Layer w11.81: U1.28@1222.78,540.97 1279.45,597.64 ; 1279.45,600.07 1286.46,607.08 v3@1286.46,628.27
  Top Layer w15.75: U1.28 U1.28@1222.78,540.97 ; 1279.45,597.64 1279.45,600.07 ; v3(1284.72,630) v3@1286.46,628.27
  Bottom Layer w19.68: v3(1284.72,630) 1284.72,734.25 1325.69,775.22 1338.99,775.22 1358.78,795.01 1358.78,808.31 1375.47,825 J2.14
PC13: J3.4 U1.2 | length 684.7
  Top Layer w15.75: J3.4 445,138.41 454.22,147.64 569.85,147.64 578.74,156.52 578.74,273.62 679.13,374.02 795.48,374.02 795.57,373.93 863.65,373.93 U1.2
SWCLK: J4.2 U1.37 | length 1181
  Top Layer w11.81: v2(324.8,442.91) 327.48,445.59 371.77,445.59 487.2,561.02 504.65,561.02 507.34,558.34 v2(534.18,558.34) ; v2(974.41,505.91) 974.41,526.88 1052.34,604.8 1052.34,625.78 U1.37
  Bottom Layer w11.81: J4.2 100.59,485 142.68,442.91 v2(324.8,442.91) ; v2(534.18,558.34) 542.18,566.34 806.64,566.34 867.08,505.91 v2(974.41,505.91)
SWDIO: J4.3 U1.34 | length 1269.2
  Top Layer w11.81: v2(433.07,472.44) 503.22,542.59 571.5,542.59 662.77,633.86 744.09,633.86 v2(777.56,600.39) ; v2(1062.99,521.65) 1107.46,566.12 1107.46,589.89 U1.34
  Bottom Layer w11.81: J4.3 345.63,385 v2(433.07,472.44) ; v2(777.56,600.39) 850.93,600.39 929.67,521.65 v2(1062.99,521.65)
XTALA: C9.2 R2.1 U1.5 Y1.1 | length 1313.5
  Top Layer w11.81: v2(285.43,344.49) 285.43,425.81 322.96,463.34 361.1,463.34 375,477.24 Y1.1 ; v2(452.76,206.69) 452.76,275.59 v2(482.28,305.12) ; v2(817.65,245.35) 818.59,245.35 U1.5
  Bottom Layer w11.81: v2(285.43,344.49) 296.94,332.99 296.94,310.71 400.96,206.69 v2(452.76,206.69) ; v2(482.28,305.12) 482.28,287.4 R2.1 505.9,267.71 582.67,190.94 636.44,190.94 654.92,209.42 654.92,268.67 661.84,275.59 698.82,275.59 727.76,246.65 816.34,246.65 v2(817.65,245.35)
XTALB: C10.2 R2.2 U1.6 Y1.2 | length 918.2
  Top Layer w11.81: v2(314.96,314.96) 360.04,314.96 Y1.2 Y1.2@380.12,305.12 ; v2(629.92,206.69) 688.98,206.69 v2(708.66,187.01) ; v2(866.14,265.75) 866.83,265.75 U1.6
  Bottom Layer w11.81: v2(314.96,314.96) 388.73,388.73 459.28,388.73 468.5,379.5 468.5,372.04 498.03,342.52 R2.2 505.9,342.52 525.59,322.83 525.59,318.89 578.73,265.75 C10.2 620.08,216.54 v2(629.92,206.69) ; v2(708.66,187.01) 787.4,187.01 v2(866.14,265.75)
XTALC: U1.3 Y2.1 | length 170.7
  Top Layer w15.75: Y2.1 842.37,324.8 U1.3
XTALD: U1.4 Y2.4 | length 239
  Top Layer w15.75: Y2.4 757.87,210.63 917.22,369.98 U1.4
pads on no net: J1.4 J2. J3. J4.

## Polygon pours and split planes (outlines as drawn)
GND on Top Layer "GND_L01_P001" (solid, pour order 1): 0,905.51 0,0 2106.3,0 2106.3,905.51
GND on Bottom Layer "GND_L02_P003" (solid, pour order 3): 0,905.51 0,0 2106.3,0 2106.3,905.51

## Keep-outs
Keep-Out Layer:
  the board outline again, w5

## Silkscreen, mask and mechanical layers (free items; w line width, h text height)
Top Overlay:
  text "3V3" at 1781.3,816.93 h18 r90
  text "GND" at 88.39,807.09 h18 r90
  text "3V3" at 176.97,807.09 h18 r90
  text "PB7" at 275.59,807.09 h18 r90
  text "PB6" at 373.82,807.09 h18 r90
  text "PB5" at 482.09,807.09 h18 r90
  text "PB4" at 580.71,807.09 h18 r90
  text "PB3" at 678.94,807.09 h18 r90
  text "PA15" at 777.37,807.09 h18 r90
  text "PA12" at 875.98,807.09 h18 r90
  text "PA11" at 974.41,807.09 h18 r90
  text "PA10" at 1082.48,807.09 h18 r90
  text "PA9" at 1180.91,807.09 h18 r90
  text "PA8" at 1279.34,807.09 h18 r90
  text "PB15" at 1377.76,807.09 h18 r90
  text "PB14" at 1476.38,807.09 h18 r90
  text "PB13" at 1584.45,807.09 h18 r90
  text "PB12" at 1683.07,807.09 h18 r90
  text "GND" at 1879.73,807.09 h18 r90
  text "GND" at 1978.15,807.09 h18 r90
  text "BOOT0" at 1656.85,384.05 h18
  text "BOOT1" at 1860.24,177.36 h18
  text "PB8" at 196.66,59.06 h18 r90
  text "PB9" at 295.08,59.06 h18 r90
  text "3V3" at 1800.99,59.06 h18 r90
  text "GND" at 1899.41,59.06 h18 r90
  text "GND" at 2007.68,59.06 h18 r90
  text "GND" at 115.59,51.63 h18 r90
  text "PV13" at 403.35,49.21 h18 r90
  text "NRST" at 501.78,49.21 h18 r90
  text "PA0" at 600.2,49.21 h18 r90
  text "PA1" at 698.82,49.21 h18 r90
  text "PA2" at 797.24,49.21 h18 r90
  text "PA3" at 895.48,49.21 h18 r90
  text "PA4" at 994.09,49.21 h18 r90
  text "PA5" at 1102.17,49.21 h18 r90
  text "PA6" at 1200.59,49.21 h18 r90
  text "PA7" at 1299.21,49.21 h18 r90
  text "PB0" at 1397.45,49.21 h18 r90
  text "PB1" at 1496.06,49.21 h18 r90
  text "PB10" at 1604.14,49.21 h18 r90
  text "PB11" at 1702.76,49.21 h18 r90
Bottom Overlay:
  lines w10: 531.5,757.87 669.29,757.87 ; 1387.8,748.03 1614.17,748.03 1624.02,738.19 ; 1732.28,738.19 1742.13,748.03 1860.24,748.03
